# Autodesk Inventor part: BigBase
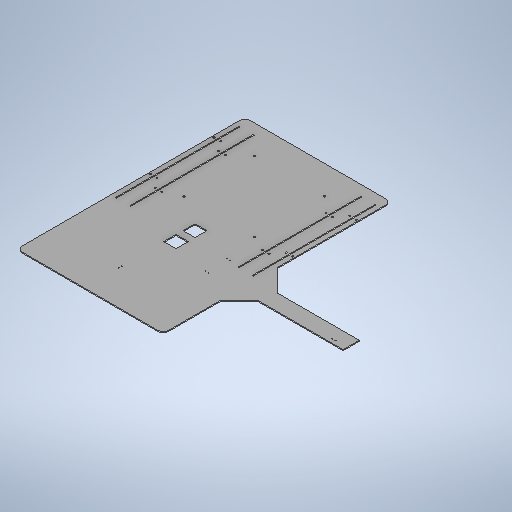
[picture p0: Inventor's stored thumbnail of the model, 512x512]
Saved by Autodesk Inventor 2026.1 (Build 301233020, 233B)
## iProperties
Created: 2026-10
Part Number: BigBase
Material: Generic
Document SubType Name: Modeling
Designer: hp
Density: 1 g/cm^3
Appearance: Default
Author: hp
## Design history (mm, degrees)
sketch "BigBaseSketch"
  geometry: L1 (0, 0)-(1200, 0); L2 (1200, 0)-(1200, 770); L3 (1200, 770)-(0, 770); L4 (0, 770)-(0, 0); L5 (150, 200)-(520, 570); L6 (520, 200)-(150, 570); C1 r 5 at (520, 200); C2 r 5 at (520, 570); C3 r 5 at (150, 200); C4 r 5 at (150, 570); 2 further points
  constraints: 12 end point, 4 centre point, 2 horizontal alignment, 2 midpoint, 2 parallel, 2 vertical alignment, 1 horizontal, 1 perpendicular
  dimensions: "d0" = 1200 distance of L3.end L2.end; "d4" = 10 diameter of C1 (= d10); "d8" = 10 diameter of C2 (= d10); "d9" = 370 distance of L5.end L6.start (= d12); "d10" = 10 diameter of C3; "d11" = 10 diameter of C4; "d12" = 370 distance of L6.end L5.start; "d13" = 370 distance of L6.end L5.end (= d9); "d39" = 200 distance from line of L5.start L1
extrude "Extrusion2" new body sketch "BigBaseSketch" distance "d14" = 5; taper "d15" = 0 deg
sketch "StorageAreaSketch"
  geometry: L1 (435, 205)-(515, 205); L2 (515, 205)-(515, 285); L3 (515, 285)-(435, 285); L4 (435, 295)-(515, 295); L5 (345, 205)-(425, 205); L6 (435, 285)-(435, 205); L7 (425, 205)-(425, 285); L8 (345, 285)-(345, 205); L9 (425, 285)-(345, 285); L10 (515, 295)-(515, 375); L11 (515, 375)-(435, 375); L12 (345, 295)-(425, 295); L13 (435, 395)-(515, 395); L14 (345, 375)-(345, 295); L15 (425, 375)-(345, 375); L16 (245, 285)-(245, 205); L17 (435, 475)-(435, 395); L18 (425, 475)-(345, 475); L19 (325, 375)-(245, 375); L20 (235, 205)-(235, 285); L21 (245, 205)-(325, 205); L22 (325, 205)-(325, 285); L23 (325, 285)-(245, 285); L24 (155, 295)-(235, 295); L25 (155, 205)-(235, 205); L26 (235, 285)-(155, 285); L27 (155, 285)-(155, 205); L28 (155, 375)-(155, 295); L29 (155, 485)-(235, 485); L30 (235, 485)-(235, 565); L31 (235, 565)-(155, 565); L32 (155, 565)-(155, 485); L33 (345, 475)-(345, 395); L34 (325, 295)-(325, 375); L35 (245, 375)-(245, 295); L36 (245, 295)-(325, 295); L37 (235, 295)-(235, 375); L38 (345, 395)-(425, 395); L39 (425, 295)-(425, 375); L40 (135, 385)-(535, 385); L41 (135, 185)-(135, 585); L42 (135, 585)-(535, 585); L43 (535, 185)-(135, 185); L44 (335, 585)-(335, 185); L45 (535, 585)-(535, 185); L46 (435, 375)-(435, 295); L47 (235, 395)-(235, 475); L48 (325, 395)-(325, 475); L49 (245, 475)-(245, 395); L50 (245, 395)-(325, 395); L51 (235, 375)-(155, 375); L52 (155, 395)-(235, 395); L53 (155, 475)-(155, 395); L54 (235, 475)-(155, 475); L55 (325, 475)-(245, 475); L56 (245, 485)-(325, 485); L57 (325, 485)-(325, 565); L58 (325, 565)-(245, 565); L59 (245, 565)-(245, 485); L60 (515, 395)-(515, 475); L61 (425, 395)-(425, 475); L62 (345, 565)-(345, 485); L63 (345, 485)-(425, 485); L64 (515, 475)-(435, 475)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; C1 r 5 at (520, 200); C2 r 5 at (150, 200); C3 r 5 at (520, 570); C4 r 5 at (150, 570); C5 r 5 at (520, 570) reference; 1 further point
  constraints: 140 end point, 4 centre point, 4 collinear, 4 horizontal, 4 midpoint, 4 parallel, 3 symmetric about line, 2 perpendicular, 2 vertical, 1 concentric, 119 other
  dimensions: "d48" = 80 distance of L31.end L30.end; "d49" = 80 distance of L30.end L29.end; "d50" = 90 distance of L29.start L52.start; "d51" = 90 distance of L29.start L56.start; "d52" = 190 distance of L29.end L24.end; "d53" = 190 distance of L29.end L63.end; "d54" = 20 distance between parallel lines of L27 L41; "d55" = 20 distance between parallel lines of L21 L43; "d56" = 20 distance between parallel lines of L10 L45; "d57" = 20 distance between parallel lines of L58 L42; "d58" = 10 diameter of C4; "d59" = 15 distance from line of L42 C4.centre (= d60); "d60" = 15 distance from line of L41 C4.centre
  node "Sketch Rectangular Pattern1" dims "d50" = 90, "d51" = 90
  node "Sketch Rectangular Pattern2" dims "d52" = 190, "d53" = 190
sketch "Sketch3"
  geometry: L1 (135, 185)-(135, 585) reference; L2 (55, 65)-(55, 705); L3 (535, 185)-(135, 185) reference; L4 (135, 585)-(535, 585) reference; L5 (135, 385)-(535, 385) reference; L6 (55, 100)-(705, 100); L7 (705, 100)-(705, 105); L8 (705, 105)-(55, 105); L9 (55, 105)-(55, 100); L10 (55, 25)-(705, 25); L11 (705, 25)-(705, 30); L12 (705, 30)-(55, 30); L13 (55, 30)-(55, 25); L14 (55, 665)-(700, 665); L15 (700, 665)-(700, 670); L16 (700, 670)-(55, 670); L17 (55, 670)-(55, 665); L18 (55, 740)-(700, 740); L19 (700, 745)-(55, 745); L20 (700, 740)-(700, 745); L21 (55, 745)-(55, 740); 3 further points
  constraints: 34 end point, 8 parallel, 4 horizontal, 4 perpendicular, 2 collinear, 2 midpoint, 1 horizontal alignment
  dimensions: "d64" = 640 distance of L2.end L2.start; "d65" = 80 distance between parallel lines of L1 L2; "d129" = 650 distance of L8.end L7.end; "d130" = 5 distance of L7.end L6.end; "d131" = 80 distance between parallel lines of L1 L9; "d132" = 80 distance between parallel lines of L8 L3; "d133" = 650 distance of L12.end L11.end (derived); "d134" = 5 distance of L11.end L10.end; "d135" = 70 distance between parallel lines of L6 L12; "d138" = 645 distance of L16.end L15.end; "d139" = 5 distance of L15.end L14.end; "d140" = 645 distance of L19.end L19.start; "d141" = 5 distance of L19.start L18.end; "d142" = 80 distance between parallel lines of L4 L14; "d143" = 80 distance between parallel lines of L17 L1; "d144" = 70 distance between parallel lines of L16 L18
extrude "Extrusion3" cut sketch "Sketch3" extent not by distance; stored distance "d101" = 0; taper "d102" = 0 deg
sketch "Sketch4"
  geometry: L1 (535, 585)-(535, 185) reference; L2 (715, 352.5)-(780, 352.5); L3 (780, 352.5)-(780, 417.5); L4 (780, 417.5)-(715, 417.5); L5 (715, 417.5)-(715, 352.5); L6 (780, 417.5)-(780, 352.5); L7 (679, 353.5)-(616, 353.5); L8 (616, 353.5)-(616, 416.5); L9 (616, 416.5)-(679, 416.5); L10 (679, 416.5)-(679, 353.5); L11 (679, 353.5)-(616, 416.5); L12 (616, 353.5)-(679, 416.5); C1 r 31.5 at (647.5, 385); 9 further points
  constraints: 22 end point, 5 midpoint, 4 parallel, 2 horizontal, 2 horizontal alignment, 2 perpendicular, 1 centre point, 1 coincident
  dimensions: "d110" = 63 diameter of C1; "d111" = 112.5 distance from line of L1 C1.centre; "d119" = 65 distance of L4.end L3.end; "d120" = 65 distance of L3.end L2.end; "d121" = 67.5 distance from line of C1.centre L5; "d145" = 63 distance of L7.end L8.end (derived); "d146" = 63 distance of L8.end L9.end (derived)
extrude "Extrusion4" cut sketch "Sketch4" extent not by distance; stored distance "d112" = 0; taper "d113" = 0 deg
fillet "Fillet1" dims "d147" = 30
sketch "Sketch5"
  geometry: L1 (715, 352.5)-(715, 417.5) reference; L2 (780, 417.5)-(780, 352.5) reference; L3 (715, 417.5)-(780, 417.5); L4 (780, 417.5)-(780, 1317.5); L5 (780, 1317.5)-(715, 1317.5); L6 (715, 1317.5)-(715, 417.5); L7 (1170, 770)-(30, 770) reference; L8 (899.316, 770)-(780, 889.316); L9 (747.5, 417.5)-(747.5, 1317.5); L10 (595.684, 770)-(715, 889.316); L11 (800, 417.5)-(800, 1317.5); L12 (800, 1317.5)-(780, 1317.5); L13 (800, 417.5)-(780, 417.5); 8 further points
  constraints: 20 end point, 2 horizontal, 2 midpoint, 2 parallel, 2 perpendicular, 2 point on line, 2 symmetric about line, 1 collinear, 1 vertical
  dimensions: "d148" = 900 distance of L4.start L4.end; "d158" = 45 deg angle of L7 L8; "d166" = 20 distance of L11.start L4.start
extrude "Extrusion5" join sketch "Sketch5" distance "d149" = 5; taper "d150" = 0 deg
sketch "Sketch6"
  geometry: 16 further points
hole "Hole1" sketch "Sketch6" at (-507.5, 10), (-172.5, 10), (-172.5, 45), (-222.5, 85), (-507.5, 45), (-557.5, 85), (-557.5, 120), (-222.5, 120), (-557.5, 650), (-557.5, 685), (-222.5, 650), (-222.5, 685)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 diameter "d151" = 9; stored, may be unused: countersink angle "d155" = 90 deg, drill point angle "d157" = 0 deg; dims "d152" = 6, "d153" = 4, "d154" = 2, "d156" = 8
sketch "Sketch7"
  geometry: 4 further points
hole "Hole2" sketch "Sketch7" at (-690, 597), (-690, 613), (-805, 597), (-805, 613) diameter "d159" = 4.5; stored, may be unused: countersink angle "d163" = 90 deg, drill point angle "d165" = 0 deg; dims "d160" = 6, "d161" = 4, "d162" = 2, "d164" = 8
sketch "Sketch8"
  geometry: 2 further points
hole "Hole3" sketch "Sketch8" at (-1002, 354), (-1018, 354) diameter "d167" = 4.5; stored, may be unused: countersink angle "d171" = 90 deg, drill point angle "d173" = 0 deg; dims "d168" = 6, "d169" = 4, "d170" = 2, "d172" = 8
sketch "Sketch9"
  geometry: 2 further points
hole "Hole4" sketch "Sketch9" at (-778.5, 1239.5), (-778.5, 1255.5) diameter "d174" = 4.5; stored, may be unused: countersink angle "d178" = 90 deg, drill point angle "d180" = 0 deg; dims "d175" = 6, "d176" = 4, "d177" = 2, "d179" = 8
body "Solid2"
